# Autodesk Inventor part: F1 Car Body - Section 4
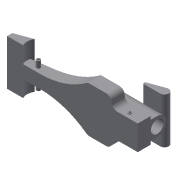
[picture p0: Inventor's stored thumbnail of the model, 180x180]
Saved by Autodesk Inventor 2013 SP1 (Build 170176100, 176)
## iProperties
Created: 2013-01
Part Number: F1 Car Body - Section 4
Material: Generic
Document SubType Name: Modeling
Designer: banachd
Density: 1 g/cm^3
Author: banachd
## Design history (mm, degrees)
sketch "Sketch1"
  geometry: L1 (0, 0)-(200, 0); L2 (200, 0)-(200, 20); L3 (200, 20)-(110, 20); L4 (0, 8)-(0, 0); A1 r 510.167 centre (110, -490.167) between (110, 20) and (0, 8)
  constraints: 8 end point, 2 perpendicular, 2 point on circle, 1 centre point, 1 horizontal, 1 parallel, 1 tangent
  dimensions: "d0" = 200 distance of L1.start L1.end; "d1" = 20 distance of L1.end L2.end; "d2" = 90 distance of L2.end L3.end; "d3" = 8 distance of L4.start L1.start
extrude "Extrusion1" new body sketch "Sketch1" distance "d4" = 35; taper "d5" = 0 deg
sketch "Sketch2"
  geometry: L1 (0, 0)-(200, 0) reference; L2 (0, 35)-(200, 35) reference; L3 (0, 0)-(0, 35) reference; L4 (0, 10)-(50, 10); L5 (200, 35)-(160, 35); L6 (160, 35)-(160, 19); L7 (160, 19)-(200, 19); L8 (200, 19)-(200, 35); A1 r 120 centre (50, 130) between (50, 10) and (123.314, 35)
  constraints: 10 end point, 3 parallel, 2 point on circle, 2 point on line, 1 centre point, 1 horizontal, 1 perpendicular, 1 tangent
  dimensions: "d6" = 50 distance of L4.start L4.end; "d7" = 40 distance of L7.end L6.end; "d8" = 16 distance of L6.end L5.end; "d9" = 10 distance between parallel lines of L4 L1; "d10" = 120 radius of A1
extrude "Extrusion2" cut sketch "Sketch2" stored distance "d11" = 0; taper "d12" = 0 deg
sketch "Sketch3"
  geometry: L1 (0, 0)-(0, 8) reference; L2 (50, 0)-(0, 0) reference; C1 r 3 at (40, 8)
  constraints: 1 centre point
  dimensions: "d13" = 6 diameter of C1; "d15" = 8 distance from line of C1.centre L2; "d17" = 40 distance from line of C1.centre L1
extrude "Extrusion3" join sketch "Sketch3" distance "d18" = 10; taper "d19" = 0 deg
hole "Hole1" diameter "d22" = 3; stored, may be unused: countersink angle "d26" = 90 deg, drill point angle "d28" = 118 deg; dims "d20" = 10, "d21" = 10, "d23" = 6, "d24" = 4, "d25" = 2, "d27" = 8
pattern_linear "Rectangular Pattern1"
fillet "Fillet1" dims "d32" = 8
mirror "Mirror1"
sketch "Sketch4"
  geometry: L1 (38, 20)-(0, 20) reference; L2 (5, 20)-(5, 30); L3 (33, 30)-(33, 20); L4 (-8, 0)-(-16, 0) reference; A1 r 14 centre (19, 30) between (33, 30) and (5, 30); 2 further points
  constraints: 4 end point, 2 perpendicular, 2 point on circle, 2 point on line, 2 tangent, 1 centre point, 1 midpoint, 1 vertical alignment
  dimensions: "d33" = 30 distance from line of A1.centre L4; "d34" = 14 radius of A1
extrude "Extrusion4" join sketch "Sketch4" distance "d35" = 80; taper "d36" = 0 deg
sketch "Sketch5"
  geometry: L1 (0, 0)-(0, 8) reference; L2 (110, 20)-(120, 20) reference; L3 (120, 20)-(120, 44) reference; L4 (120, 44)-(200, 44) reference; L5 (200, 44)-(200, 0) reference; L6 (200, 0)-(0, 0) reference; L7 (0, 8)-(25.066, 17.123); L8 (168.592, 41)-(193.592, 41); L9 (191.4, 53.43)-(167.908, 44.879); C1 r 1.5 at (180, 8) reference; C2 r 1.5 at (40, 8) reference; A1 r 510.167 centre (110, -490.167) between (110, 20) and (0, 8) reference; A2 r 17.5 centre (40, 8) between (25.066, 17.123) and (24.436, 0); A3 r 6.408 centre (193.592, 47.408) between (193.592, 41) and (191.4, 53.43); A4 r 2 centre (168.592, 43) between (167.908, 44.879) and (168.592, 41)
  constraints: 6 end point, 6 point on circle, 5 tangent, 3 centre point, 1 coincident, 1 parallel, 1 point on line
  dimensions: "d37" = 17.5 radius of A2; "d38" = 25 distance of L8.start L8.end; "d39" = 2 radius of A4; "d40" = 20 deg angle of L8 L9; "d41" = 20 deg angle of L6 L7; "d42" = 3 distance between parallel lines of L8 L4
  node "Project Cut Edges1"
extrude "Extrusion5" join sketch "Sketch5" stored distance "d43" = 70; taper "d44" = 0 deg
extrude "Extrusion6" join sketch "Sketch5" stored distance "d45" = 70; taper "d46" = 0 deg
hole "Hole2" diameter "d49" = 19.5; stored, may be unused: countersink angle "d53" = 90 deg, drill point angle "d55" = 118 deg; dims "d47" = 10, "d48" = 10, "d50" = 6, "d51" = 4, "d52" = 2, "d54" = 55
body "Solid1"
